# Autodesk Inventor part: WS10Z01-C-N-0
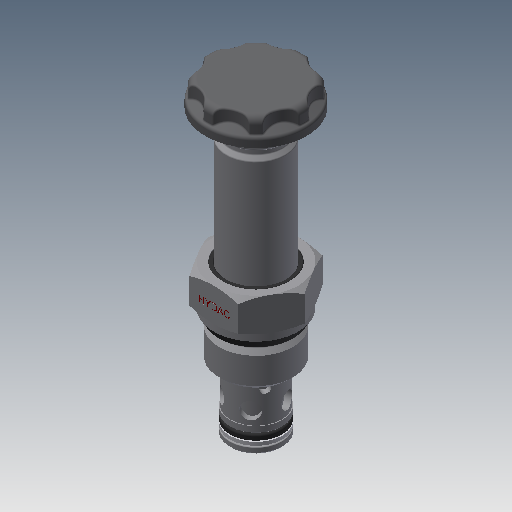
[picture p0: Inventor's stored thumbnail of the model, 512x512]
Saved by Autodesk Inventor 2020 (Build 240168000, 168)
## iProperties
DataBaseUnit: MM
Created: 2015-05
Part Number: WS10Z01-C-N-0
Material: Generico
Document SubType Name: Modeling
Designer: Carlo
Density: 1 g/cm^3
Appearance: Default
Author: Windows User
Title: SW3DPS-10000318189-SWB-000_01-DEFAULT.step
Description: STEP AP214
Creation Date: 2014-11-27
Sending System: SolidWorks 2015
Preprocessor: SwSTEP 2.0
Author: Carlo
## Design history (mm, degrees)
feature "Base1"
node "Piano di lavoro1"
node "Piano di lavoro2"
node "Asse di lavoro1"
node "Imported1"
other parameters: "d0" = 0, "d1" = 0
